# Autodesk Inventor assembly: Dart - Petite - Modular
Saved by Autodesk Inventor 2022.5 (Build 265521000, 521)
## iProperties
Created: 2025-01
Part Number: Dart - Petite - Modular
Document SubType Name: Assembly
Designer: AdminForWorker
Title: Dart - Petite - Modular v8
Author: AdminForWorker
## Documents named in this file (4)
- c:\worker\convert-fusion-r06-cosv3\tmp\job-1\21\temp\files\23c0a705-9e7e-43f9-b191-1b8d9b6455f5\cbf05cd7-f9f3-42d1-bd02-f745c6532357.iam
- c:\worker\convert-fusion-r06-cosv3\tmp\job-1\21\temp\files\23c0a705-9e7e-43f9-b191-1b8d9b6455f5\Modular - Placebo - Bayonet Connector v4.ipt
- c:\worker\convert-fusion-r06-cosv3\tmp\job-1\21\temp\files\23c0a705-9e7e-43f9-b191-1b8d9b6455f5\Dart Petite Modular.ipt
- c:\worker\convert-fusion-r06-cosv3\tmp\job-1\21\temp\files\23c0a705-9e7e-43f9-b191-1b8d9b6455f5\Modular - Placedo - Cord Set v4.ipt
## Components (3 placed, 3 different names)
1. Modular - Placebo - Bayonet Connector v4:1
2. Dart Petite Modular:1
3. Modular - Placedo - Cord Set v4:1
